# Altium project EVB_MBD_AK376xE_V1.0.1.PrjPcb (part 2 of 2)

## Sheet JTAG_I2S_KEY.SchDoc: EVB_MBD_AK376xE_V1.0.1
size A3; Revision: V1.0.1; SheetNumber: 8; SheetTotal: 8
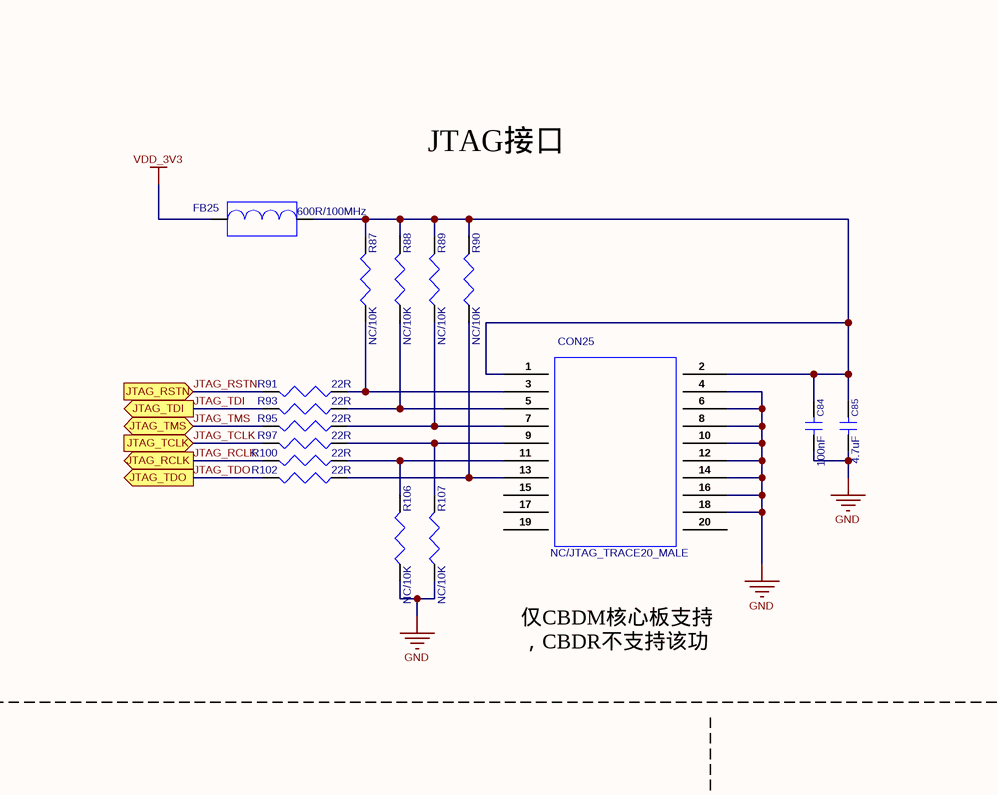
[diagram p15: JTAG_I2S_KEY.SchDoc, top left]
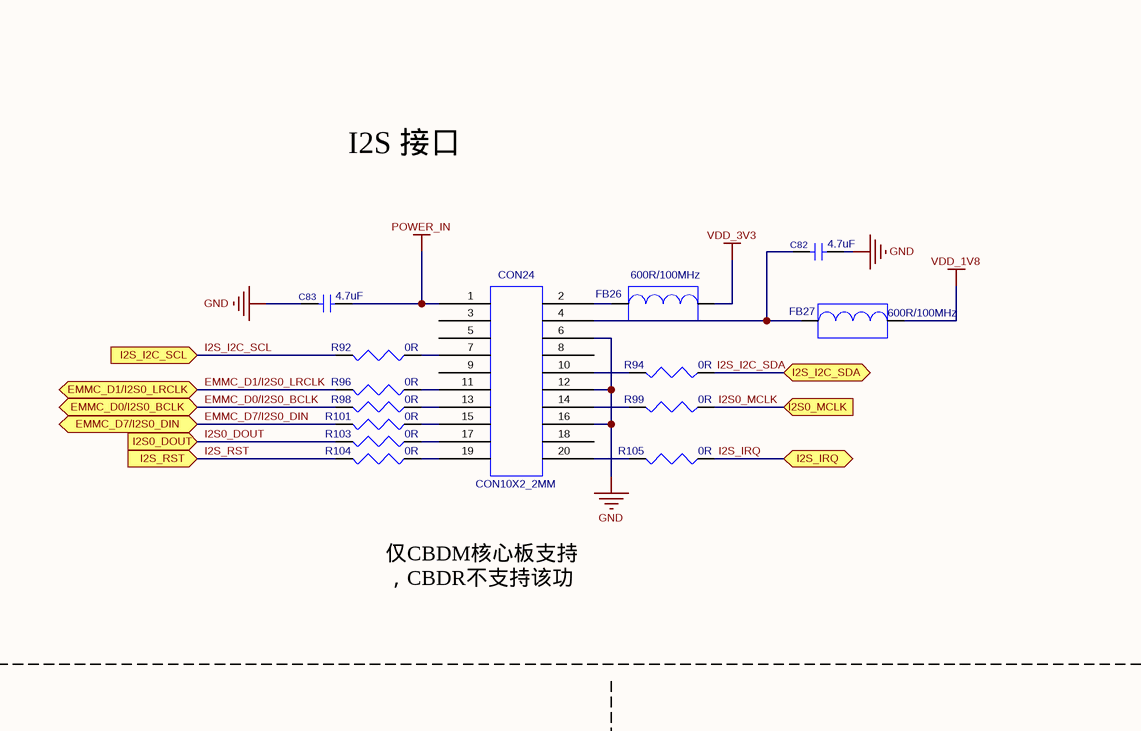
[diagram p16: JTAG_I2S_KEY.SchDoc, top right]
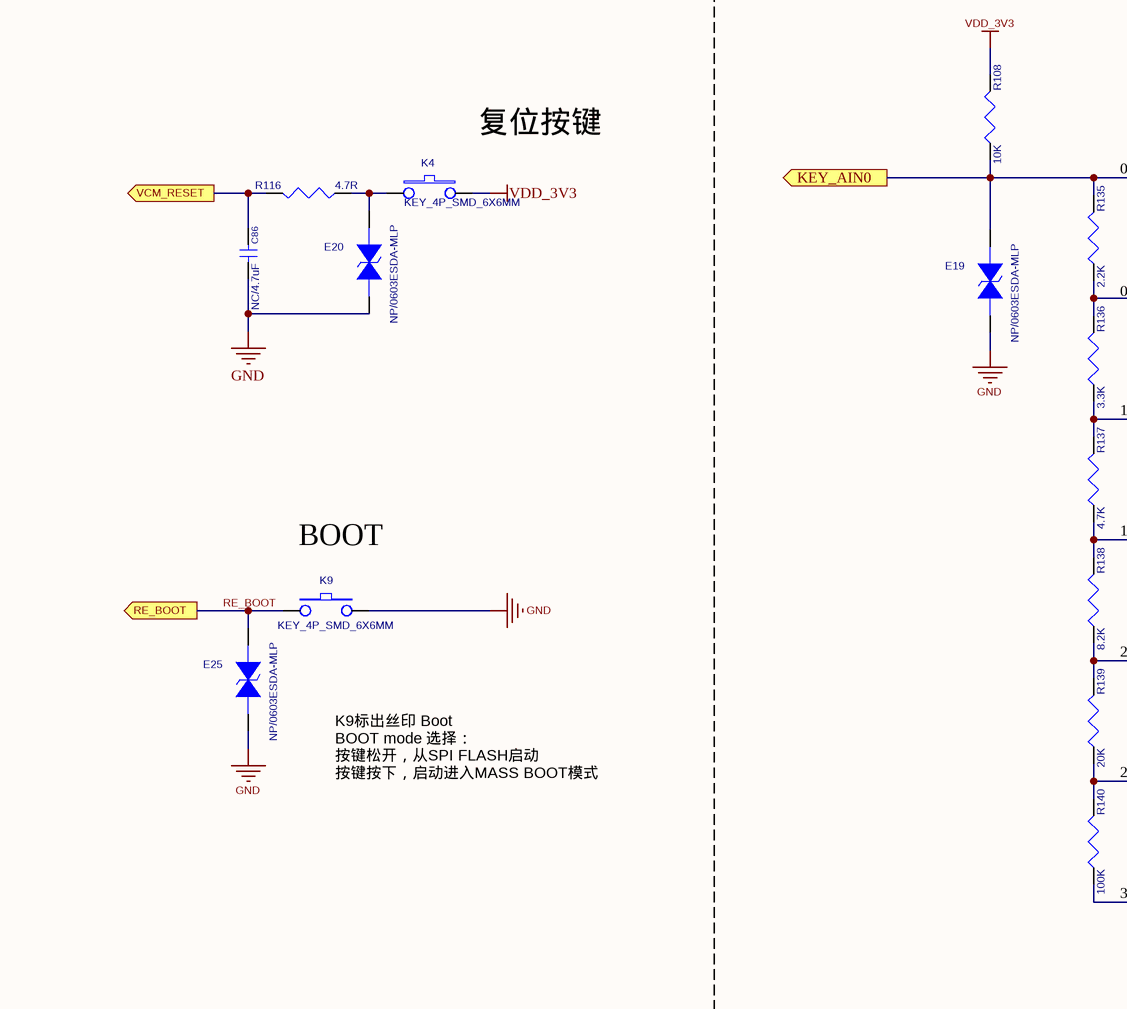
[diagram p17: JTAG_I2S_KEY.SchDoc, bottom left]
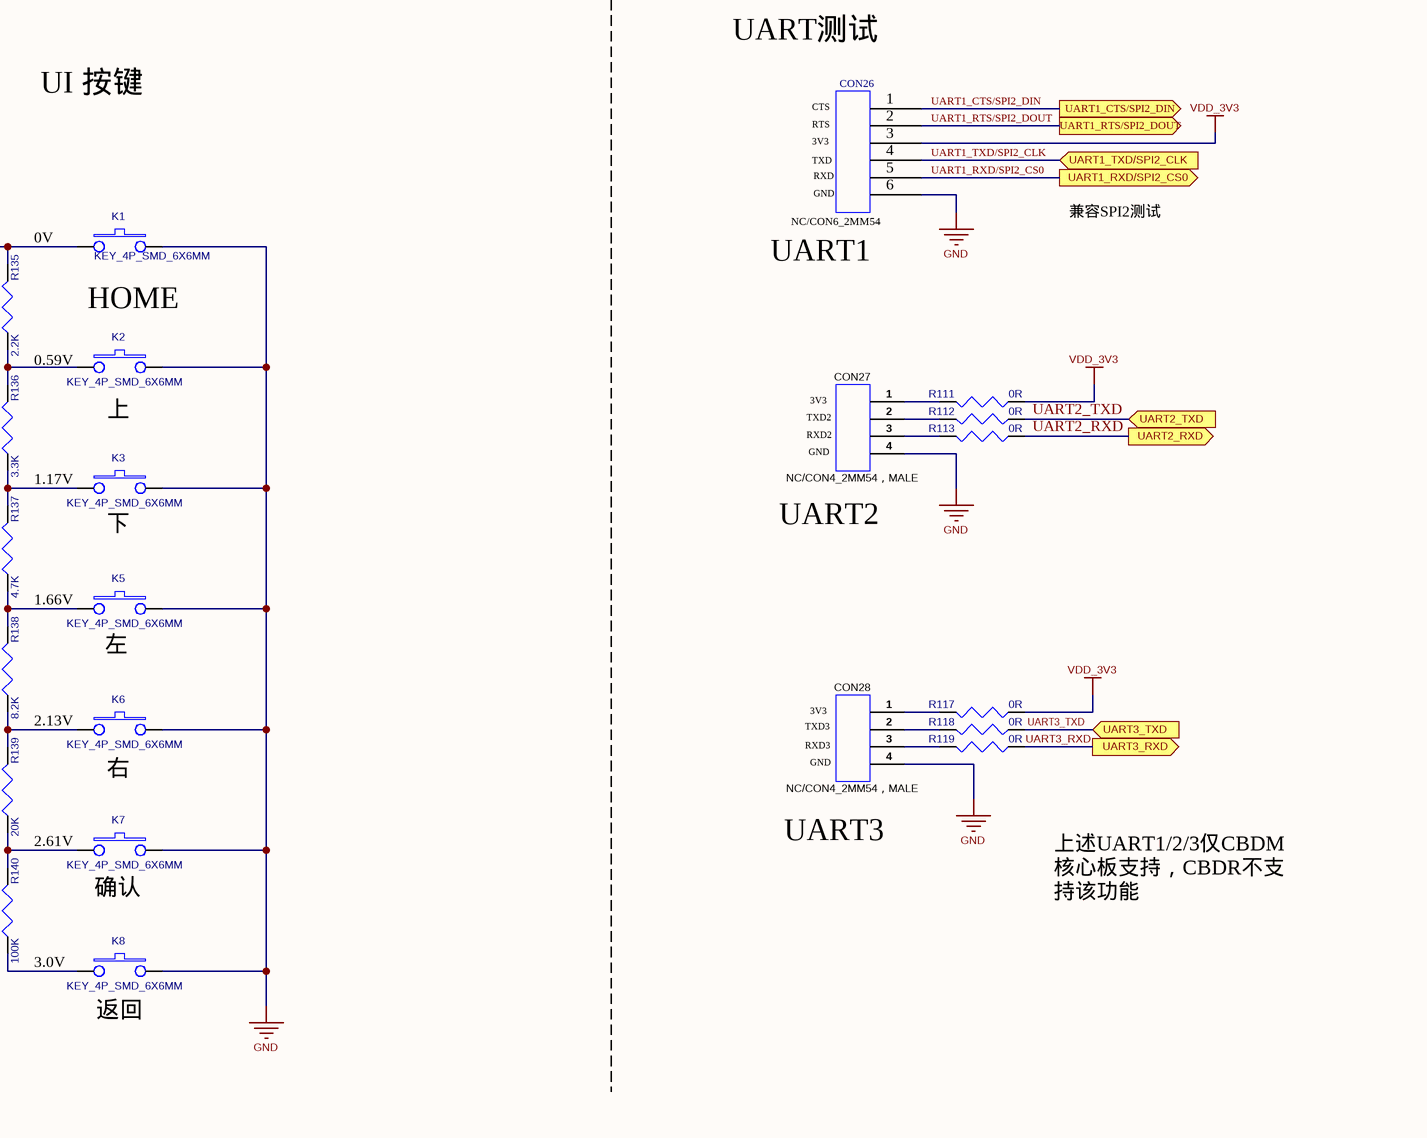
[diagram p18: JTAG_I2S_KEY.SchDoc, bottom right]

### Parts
C82  4.7uF  [C0603]
C83  4.7uF  [C0603]
C84  100nF  [C0603]
C85  4.7uF  [C0603]
C86  NC/4.7uF  [C0603]
CON24  value CON10X2_2MM  [CON10X2_2MM0]  (hidden comment: CON10X2_2MM0)
CON25  NC/JTAG_TRACE20_MALE  [JTAG_TRACE20_MALE]
CON26  NC/CON6_2MM54  [CON6_2MM54]
CON27  NC/CON4_2MM54，MALE  [CON4_2MM54]
CON28  NC/CON4_2MM54，MALE  [CON4_2MM54]
E19  value NP/0603ESDA-MLP  [ESD0603]  (hidden comment: ESD0603)
E20  value NP/0603ESDA-MLP  [ESD0603]  (hidden comment: ESD0603)
E25  value NP/0603ESDA-MLP  [ESD0603]  (hidden comment: ESD0603)
FB25  600R/100MHz  [FB0603]
FB26  600R/100MHz  [FB0603]
FB27  600R/100MHz  [FB0603]
K1  KEY_4P_SMD_6X6MM  [KEY_4P_SMD_6X6MM]
K2  KEY_4P_SMD_6X6MM  [KEY_4P_SMD_6X6MM]
K3  KEY_4P_SMD_6X6MM  [KEY_4P_SMD_6X6MM]
K4  KEY_4P_SMD_6X6MM  [KEY_4P_SMD_6X6MM]
K5  KEY_4P_SMD_6X6MM  [KEY_4P_SMD_6X6MM]
K6  KEY_4P_SMD_6X6MM  [KEY_4P_SMD_6X6MM]
K7  KEY_4P_SMD_6X6MM  [KEY_4P_SMD_6X6MM]
K8  KEY_4P_SMD_6X6MM  [KEY_4P_SMD_6X6MM]
K9  KEY_4P_SMD_6X6MM  [KEY_4P_SMD_6X6MM]
R87  NC/10K  [R0603]
R88  NC/10K  [R0603]
R89  NC/10K  [R0603]
R90  NC/10K  [R0603]
R91  22R  [R0603]
R92  0R  [R0603]
R93  22R  [R0603]
R94  0R  [R0603]
R95  22R  [R0603]
R96  0R  [R0603]
R97  22R  [R0603]
R98  0R  [R0603]
R99  0R  [R0603]
R100  22R  [R0603]
R101  0R  [R0603]
R102  22R  [R0603]
R103  0R  [R0603]
R104  0R  [R0603]
R105  0R  [R0603]
R106  NC/10K  [R0603]
R107  NC/10K  [R0603]
R108  10K  [R0603]
R111  0R  [R0603]
R112  0R  [R0603]
R113  0R  [R0603]
R116  4.7R  [R0603]
R117  0R  [R0603]
R118  0R  [R0603]
R119  0R  [R0603]
R135  2.2K  [R0603]
R136  3.3K  [R0603]
R137  4.7K  [R0603]
R138  8.2K  [R0603]
R139  20K  [R0603]
R140  100K  [R0603]

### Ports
EMMC_D0/I2S0_BCLK (bidir), EMMC_D1/I2S0_LRCLK (bidir), EMMC_D7/I2S0_DIN (bidir), I2S0_DOUT (in), I2S0_MCLK (in), I2S_I2C_SCL (in), I2S_I2C_SDA (bidir), I2S_IRQ (bidir), I2S_RST (in), JTAG_RCLK (out), JTAG_RSTN (in), JTAG_TCLK (in), JTAG_TDI (out), JTAG_TDO (out), JTAG_TMS (bidir), KEY_AIN0 (out), RE_BOOT (out), UART1_CTS/SPI2_DIN (out), UART1_RTS/SPI2_DOUT (out), UART1_RXD/SPI2_CS0 (out), UART1_TXD/SPI2_CLK (in), UART2_RXD (out), UART2_TXD (in), UART3_RXD (out), UART3_TXD (in), VCM_RESET (out)

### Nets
GND: C82.2 C83.1 C84.2 C85.2 C86.2 CON24.6 CON24.12 CON24.16 CON25.4 CON25.6 CON25.8 CON25.10 CON25.12 CON25.14 CON25.16 CON25.18 CON26.6 CON27.4 CON28.4 E19.2 E20.2 E25.2 K1.2 K2.2 K3.2 K5.2 K6.2 K7.2 K8.2 K9.1 R106.1 R107.1
POWER_IN: C83.2 CON24.1
VDD_1V8: FB27.2
VDD_3V3: CON26.3 FB25.1 FB26.2 K4.2 R108.2 R111.1 R117.1
EMMC_D0/I2S0_BCLK: R98.2 ; port EMMC_D0/I2S0_BCLK
EMMC_D1/I2S0_LRCLK: R96.2 ; port EMMC_D1/I2S0_LRCLK
EMMC_D7/I2S0_DIN: R101.2 ; port EMMC_D7/I2S0_DIN
I2S0_DOUT: R103.2 ; port I2S0_DOUT
I2S0_MCLK: R99.1 ; port I2S0_MCLK
I2S_I2C_SCL: R92.2 ; port I2S_I2C_SCL
I2S_I2C_SDA: R94.1 ; port I2S_I2C_SDA
I2S_IRQ: R105.1 ; port I2S_IRQ
I2S_RST: R104.2 ; port I2S_RST
JTAG_RCLK: R100.2 ; port JTAG_RCLK
JTAG_RSTN: R91.2 ; port JTAG_RSTN
JTAG_TCLK: R97.2 ; port JTAG_TCLK
JTAG_TDI: R93.2 ; port JTAG_TDI
JTAG_TDO: R102.2 ; port JTAG_TDO
JTAG_TMS: R95.2 ; port JTAG_TMS
RE_BOOT: E25.1 K9.2 ; port RE_BOOT
UART1_CTS/SPI2_DIN: CON26.1 ; port UART1_CTS/SPI2_DIN
UART1_RTS/SPI2_DOUT: CON26.2 ; port UART1_RTS/SPI2_DOUT
UART1_RXD/SPI2_CS0: CON26.5 ; port UART1_RXD/SPI2_CS0
UART1_TXD/SPI2_CLK: CON26.4 ; port UART1_TXD/SPI2_CLK
UART2_RXD: R113.1 ; port UART2_RXD
UART2_TXD: R112.1 ; port UART2_TXD
UART3_RXD: R119.1 ; port UART3_RXD
UART3_TXD: R118.1 ; port UART3_TXD
NetC82_1: C82.1 CON24.4 FB27.1
NetC84_1: C84.1 C85.1 CON25.1 CON25.2 FB25.2 R87.2 R88.2 R89.2 R90.2
NetC86_1: C86.1 R116.2 ; port VCM_RESET
NetCON1_1: E19.1 K1.1 R108.1 R135.2 ; port KEY_AIN0
NetCON24_2: CON24.2 FB26.1
NetCON24_7: CON24.7 R92.1
NetCON24_10: CON24.10 R94.2
NetCON24_11: CON24.11 R96.1
NetCON24_13: CON24.13 R98.1
NetCON24_14: CON24.14 R99.2
NetCON24_15: CON24.15 R101.1
NetCON24_17: CON24.17 R103.1
NetCON24_19: CON24.19 R104.1
NetCON24_20: CON24.20 R105.2
NetCON25_3: CON25.3 R87.1 R91.1
NetCON25_5: CON25.5 R88.1 R93.1
NetCON25_7: CON25.7 R89.1 R95.1
NetCON25_9: CON25.9 R97.1 R107.2
NetCON25_11: CON25.11 R100.1 R106.2
NetCON25_13: CON25.13 R90.1 R102.1
NetCON27_1: CON27.1 R111.2
NetCON27_2: CON27.2 R112.2
NetCON27_3: CON27.3 R113.2
NetCON28_1: CON28.1 R117.2
NetCON28_2: CON28.2 R118.2
NetCON28_3: CON28.3 R119.2
NetE20_1: E20.1 K4.1 R116.1
NetK2_1: K2.1 R135.1 R136.2
NetK3_1: K3.1 R136.1 R137.2
NetK5_1: K5.1 R137.1 R138.2
NetK6_1: K6.1 R138.1 R139.2
NetK7_1: K7.1 R139.1 R140.2
NetK8_1: K8.1 R140.1

Not connected (* = marked no-connect by the designer): CON24 3 5 8 9 18; CON25 15 17 19 20

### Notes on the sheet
- JTAG接口
- I2S 接口
- 仅CBDM核心板支持，CBDR不支持该功能
- UART测试
- UI 按键
- (near CON26) 3V3
- (near CON26) RTS
- (near CON26) CTS
- (near K4) 复位按键
- (near CON26) TXD
- (near CON26) RXD
- (near CON26) GND
- 兼容SPI2测试
- 0V
- HOME
- (near CON26) UART1
- 0.59V
- (near CON27) 3V3
- 1.17V
- (near K2) 上
- (near CON27) TXD2
- (near CON27) RXD2
- (near CON27) GND
- (near K3) 下
- (near CON27) UART2
- (near K9) BOOT
- (near K5) 1.66V
- (near K5) 左
- 2.13V
- (near CON28) TXD3
- (near CON28) RXD3
- (near CON28) 3V3
- K9标出丝印 Boot
- BOOT mode 选择：
- 按键松开，从SPI FLASH启动
- (near K6) 右
- (near CON28) GND
- 按键按下，启动进入MASS BOOT模式
- 2.61V
- (near K7) 确认
- (near CON28) UART3
- 上述UART1/2/3仅CBDM核心板支持，CBDR不支持该功能
- 3.0V
- (near K8) 返回

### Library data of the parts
C82 C83 C85 = CC0304750XX: C/C,4.7uF,25V,+/-5%,0603; Catalog: 陶瓷电容
C84 = CC0301040XX: C/C,100nF,25V,+/-5%,0603; Catalog: 陶瓷电容
C86 = CC0304750XX: C/C,4.7uF,25V,+/-5%,0603; Remark: NC; Catalog: 陶瓷电容
CON24 = CNHEF2001XX: Header,Female,CON10X2,2.0mm,20pin,排母; SOURCE_PATH: E:\工作目录\ORCAD原理图库\ORCAD元件库\CONNECTOR.OLB; Catalog: Connector
CON25 = CNHEM2000XX: Header,2X10pin,2.54mm,Male,排针; SOURCE_PATH: E:\工作目录\ORCAD原理图库\ORCAD元件库\CONNECTOR.OLB; PCB DECAL: JTAG_TRACE20_2MM54_MALE; Remark: NC; Catalog: Connector
CON26 = CNHEM0600XX: Header,Male,CON1X6,2.54mm,6pin，排针; Remark: NC; Catalog: Connector
CON27 CON28 = CNHEM0400XX: Header,1X4pin,2.54mm,Male，排针; Remark: NC; Catalog: Connector
E19 E20 E25 = ED0314000XX: PESD1608H140CR15GPT,0603; ROOM: power; Source_Path: F:\PROJECTFILES\CADENCE\AK9802PLATFORM\AK98XX_MB_V0-0715.DSN; Remark: NC; Catalog: ESD Protectors
FB25-FB27 = BE0306011XX: BLM18BD601SN1, 600R@100MHz; SOURCE_PATH: D:\PROGRAM FILES\ORCAD\ORCAD_10.5\TOOLS\CAPTURE\LIBRARY\DISCRETE.OLB; Catalog: 贴片磁珠
K1-K9 = SWKS04001XX: Catalog: 开关
R87-R90 R106 R107 = CR0310020XX: Res,10K,1/10W,+/-1%,0603; Remark: NC; Catalog: 贴片电阻
R91 R93 R95 R97 R100 R102 = CR0302200XX: Res,22R,1/10W,+/-5%,0603; Catalog: 贴片电阻
R92 R94 R96 R98 R99 R101 R103-R105 R111-R113 R117-R119 = CR0300000XX: Res,0R,1/10W,+/-5%,0603; Catalog: 贴片电阻
R108 = CR0310020XX: Res,10K,1/10W,+/-1%,0603; Catalog: 贴片电阻
R116 = CR0304R70XX: Res,4.7R,1/10W,+/-5%,0603; Catalog: 贴片电阻
R135 = CR0302221XX: Res,2.2K,1/10W,+/-1%,0603; Catalog: 贴片电阻
R136 = CR0333010XX: Res,3.3K,1/10W,+/-1%,0603; Catalog: 贴片电阻
R137 = CR0347010XX: Res,4.7K,1/10W,+/-1%,0603; Catalog: 贴片电阻
R138 = CR0308221XX: Res,8.2K,1/10W,+/-1%,0603; Catalog: 贴片电阻
R139 = CR0320020XX: Res,20K,1/10W,+/-1%,0603; Catalog: 贴片电阻
R140 = CR0310030XX: Res,100K,1/10W,+/-1%,0603; Catalog: 贴片电阻

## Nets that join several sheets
GND: INTERFACE_CORE (33 pins), POWER (52 pins), TF_PA_UART (64 pins), MAC_EMMC_USBWIFI (103 pins), LCD (44 pins), JTAG_I2S_KEY (32 pins)
POWER_IN: POWER (14 pins), TF_PA_UART (C55.1 FB14.1), LCD (FB28.1 Q5.D R122.1), JTAG_I2S_KEY (C83.2 CON24.1)
VCC_3V6: INTERFACE_CORE (CON2.2 CON2.4), POWER (9 pins)
VCC_RTC: INTERFACE_CORE (CON2.3 CON2.5), POWER (BT1.1)
VDD_1V8: POWER (C23.2 C24.1 U4.5), JTAG_I2S_KEY (FB27.2)
VDD_3V3: INTERFACE_CORE (CON2.8 CON2.10), POWER (8 pins), TF_PA_UART (5 pins), MAC_EMMC_USBWIFI (5 pins), LCD (R85.2 R123.1), JTAG_I2S_KEY (7 pins)
VDDIO_CSI: POWER (JP5.3), LCD (C89.1 CON29.2)
VDDIO_CSI0: INTERFACE_CORE (CON2.6), POWER (JP5.2)
WIFI_3V3: POWER (7 pins), MAC_EMMC_USBWIFI (FB18.1 FB19.1 FB22.1 FB23.1)
AK_DM: INTERFACE_CORE (CON1.40), POWER (CON7.2 JP1.2)
AK_DP: INTERFACE_CORE (CON1.38), POWER (CON7.3 JP2.2)
CSI0_I2C_SCL: INTERFACE_CORE (CON2.36), LCD (CON29.8)
CSI0_I2C_SDA: INTERFACE_CORE (CON2.35), LCD (CON29.7)
CSI0_PCLK: INTERFACE_CORE (CON2.38), LCD (CON29.11)
CSI0_PDWN: INTERFACE_CORE (CON2.33), LCD (CON29.6)
CSI0_REST: INTERFACE_CORE (CON2.34), LCD (CON29.5)
CSI0_SCLK: INTERFACE_CORE (CON2.37), LCD (CON29.12)
EMMC_CLK: INTERFACE_CORE (CON2.21), MAC_EMMC_USBWIFI (R63.2)
EMMC_CMD: INTERFACE_CORE (CON2.18), MAC_EMMC_USBWIFI (R64.1)
EMMC_D0/I2S0_BCLK: INTERFACE_CORE (CON2.24), MAC_EMMC_USBWIFI (R47.1), JTAG_I2S_KEY (R98.2)
EMMC_D1/I2S0_LRCLK: INTERFACE_CORE (CON2.22), MAC_EMMC_USBWIFI (R46.2), JTAG_I2S_KEY (R96.2)
EMMC_D2: INTERFACE_CORE (CON2.15), MAC_EMMC_USBWIFI (R61.2)
EMMC_D3: INTERFACE_CORE (CON2.16), MAC_EMMC_USBWIFI (R62.1)
EMMC_D4: INTERFACE_CORE (CON2.17), MAC_EMMC_USBWIFI (R51.2)
EMMC_D5: INTERFACE_CORE (CON2.19), MAC_EMMC_USBWIFI (R52.1)
EMMC_D6: INTERFACE_CORE (CON2.20), MAC_EMMC_USBWIFI (R59.2)
EMMC_D7/I2S0_DIN: INTERFACE_CORE (CON2.23), MAC_EMMC_USBWIFI (R60.1), JTAG_I2S_KEY (R101.2)
EMMC_RST: INTERFACE_CORE (CON3.35), MAC_EMMC_USBWIFI (R65.2)
HPOUT: INTERFACE_CORE (CON1.4), TF_PA_UART (C53.1)
I2S0_DOUT: INTERFACE_CORE (CON2.26), JTAG_I2S_KEY (R103.2)
I2S0_MCLK: INTERFACE_CORE (CON2.25), JTAG_I2S_KEY (R99.1)
I2S_I2C_SCL: INTERFACE_CORE (CON3.50), JTAG_I2S_KEY (R92.2)
I2S_I2C_SDA: INTERFACE_CORE (CON3.49), JTAG_I2S_KEY (R94.1)
I2S_IRQ: INTERFACE_CORE (CON3.48), JTAG_I2S_KEY (R105.1)
I2S_RST: INTERFACE_CORE (CON3.47), JTAG_I2S_KEY (R104.2)
JTAG_RCLK: INTERFACE_CORE (CON4.4), JTAG_I2S_KEY (R100.2)
JTAG_RSTN: INTERFACE_CORE (CON4.2), JTAG_I2S_KEY (R91.2)
JTAG_TCLK: INTERFACE_CORE (CON4.3), JTAG_I2S_KEY (R97.2)
JTAG_TDI: INTERFACE_CORE (CON4.1), JTAG_I2S_KEY (R93.2)
JTAG_TDO: INTERFACE_CORE (CON4.5), JTAG_I2S_KEY (R102.2)
JTAG_TMS: INTERFACE_CORE (CON4.6), JTAG_I2S_KEY (R95.2)
LCD_BL: INTERFACE_CORE (CON3.34), LCD (CON22.20 CON23.8)
LCD_D0: INTERFACE_CORE (CON3.8), LCD (CON23.16)
LCD_D1: INTERFACE_CORE (CON3.7), LCD (CON23.17)
LCD_D2: INTERFACE_CORE (CON3.10), LCD (CON23.18)
LCD_D3: INTERFACE_CORE (CON3.9), LCD (CON23.19)
LCD_D4: INTERFACE_CORE (CON3.12), LCD (CON23.20)
LCD_D5: INTERFACE_CORE (CON3.11), LCD (CON23.21)
LCD_D6: INTERFACE_CORE (CON3.14), LCD (CON23.22)
LCD_D7: INTERFACE_CORE (CON3.13), LCD (CON23.23)
LCD_D8: INTERFACE_CORE (CON3.16), LCD (CON23.25)
LCD_D9: INTERFACE_CORE (CON3.15), LCD (CON23.26)
LCD_D10: INTERFACE_CORE (CON3.18), LCD (CON23.27)
LCD_D11: INTERFACE_CORE (CON3.17), LCD (CON23.28)
LCD_D12: INTERFACE_CORE (CON3.20), LCD (CON23.29)
LCD_D13: INTERFACE_CORE (CON3.19), LCD (CON23.30)
LCD_D14: INTERFACE_CORE (CON3.22), LCD (CON23.31)
LCD_D15: INTERFACE_CORE (CON3.21), LCD (CON23.32)
LCD_D16: INTERFACE_CORE (CON3.24), LCD (CON23.34)
LCD_D17: INTERFACE_CORE (CON3.23), LCD (CON23.35)
LCD_D18: INTERFACE_CORE (CON3.26), LCD (CON23.36)
LCD_D19: INTERFACE_CORE (CON3.25), LCD (CON23.37)
LCD_D20: INTERFACE_CORE (CON3.28), LCD (CON23.38)
LCD_D21: INTERFACE_CORE (CON3.27), LCD (CON23.39)
LCD_D22: INTERFACE_CORE (CON3.30), LCD (CON23.40)
LCD_D23: INTERFACE_CORE (CON3.29), LCD (CON23.41)
LCD_PWR: INTERFACE_CORE (CON3.40), LCD (R124.1)
LCD_RST: INTERFACE_CORE (CON3.33), LCD (CON22.1 CON23.10)
LED_CON: INTERFACE_CORE (CON3.36), LCD (CON29.3)
LED_STATE: INTERFACE_CORE (CON3.46), LCD (R86.2)
MIPI_DSI_TXDN0: INTERFACE_CORE (CON1.8), LCD (CON22.3)
MIPI_DSI_TXDN1: INTERFACE_CORE (CON1.14), LCD (CON22.6)
MIPI_DSI_TXDN2: INTERFACE_CORE (CON1.20), LCD (CON22.9)
MIPI_DSI_TXDN3: INTERFACE_CORE (CON1.26), LCD (CON22.12)
MIPI_DSI_TXDN4: INTERFACE_CORE (CON1.32), LCD (CON22.15)
MIPI_DSI_TXDP0: INTERFACE_CORE (CON1.10), LCD (CON22.4)
MIPI_DSI_TXDP1: INTERFACE_CORE (CON1.16), LCD (CON22.7)
MIPI_DSI_TXDP2: INTERFACE_CORE (CON1.22), LCD (CON22.10)
MIPI_DSI_TXDP3: INTERFACE_CORE (CON1.28), LCD (CON22.13)
MIPI_DSI_TXDP4: INTERFACE_CORE (CON1.34), LCD (CON22.16)
NetC86_1: INTERFACE_CORE (CON1.2), JTAG_I2S_KEY (C86.1 R116.2)
NetCON1_1: INTERFACE_CORE (CON1.1), JTAG_I2S_KEY (E19.1 K1.1 R108.1 R135.2)
NetCON2_39: INTERFACE_CORE (CON2.39), LCD (R69.2 R134.2)
NetCON2_40: INTERFACE_CORE (CON2.40), LCD (R70.2 R133.2)
NetCON2_41: INTERFACE_CORE (CON2.41), LCD (R79.2 R132.2)
NetCON2_43: INTERFACE_CORE (CON2.43), LCD (R80.2 R131.2)
NetCON2_44: INTERFACE_CORE (CON2.44), LCD (R78.2 R130.2)
NetCON2_46: INTERFACE_CORE (CON2.46), LCD (R77.2 R129.2)
NetCON2_47: INTERFACE_CORE (CON2.47), LCD (R68.2 R128.2)
NetCON2_48: INTERFACE_CORE (CON2.48), LCD (R75.2 R127.2)
NetCON2_49: INTERFACE_CORE (CON2.49), LCD (R74.2 R126.2)
NetCON2_50: INTERFACE_CORE (CON2.50), LCD (R71.2 R125.2)
RE_BOOT: INTERFACE_CORE (CON1.39), JTAG_I2S_KEY (E25.1 K9.2)
RGB_PCLK/MPU_WR: INTERFACE_CORE (CON3.3), LCD (CON23.11)
RGB_VOGATE/MPU_RD: INTERFACE_CORE (CON3.2), LCD (CON23.14)
RGB_VOHSYNC/MPU_CS: INTERFACE_CORE (CON3.4), LCD (CON23.12)
RGB_VOVSYNC/MPU_A0: INTERFACE_CORE (CON3.1), LCD (CON23.13)
RMII0_50MCLK: INTERFACE_CORE (CON4.22), MAC_EMMC_USBWIFI (CON12.8)
RMII0_MDC: INTERFACE_CORE (CON4.15), MAC_EMMC_USBWIFI (CON12.9)
RMII0_MDIO: INTERFACE_CORE (CON4.14), MAC_EMMC_USBWIFI (CON12.10)
RMII0_RST: INTERFACE_CORE (CON2.11), MAC_EMMC_USBWIFI (CON12.30)
RMII0_RXD0: INTERFACE_CORE (CON4.18), MAC_EMMC_USBWIFI (CON12.25)
RMII0_RXD1: INTERFACE_CORE (CON4.19), MAC_EMMC_USBWIFI (CON12.26)
RMII0_RXDV: INTERFACE_CORE (CON4.17), MAC_EMMC_USBWIFI (CON12.27)
RMII0_RXER: INTERFACE_CORE (CON4.16), MAC_EMMC_USBWIFI (CON12.28)
RMII0_TXD0: INTERFACE_CORE (CON4.23), MAC_EMMC_USBWIFI (CON12.15)
RMII0_TXD1: INTERFACE_CORE (CON4.26), MAC_EMMC_USBWIFI (CON12.16)
RMII0_TXEN: INTERFACE_CORE (CON4.25), MAC_EMMC_USBWIFI (CON12.11)
RMII1_50MCLK: MAC_EMMC_USBWIFI (CON17.8), LCD (R68.1)
RMII1_MDC/SD2_D0: MAC_EMMC_USBWIFI (CON17.9), LCD (R70.1)
RMII1_MDIO/SD2_D1: MAC_EMMC_USBWIFI (CON17.10), LCD (R69.1)
RMII1_RST: INTERFACE_CORE (CON2.12), MAC_EMMC_USBWIFI (CON17.30)
RMII1_RXD0/SD2_D3: MAC_EMMC_USBWIFI (CON17.25), LCD (R78.1)
RMII1_RXD1/SD2_D2: MAC_EMMC_USBWIFI (CON17.26), LCD (R77.1)
RMII1_RXDV/SD2_CMD: MAC_EMMC_USBWIFI (CON17.27), LCD (R80.1)
RMII1_RXER/SD2_CLK: MAC_EMMC_USBWIFI (CON17.28), LCD (R79.1)
RMII1_TXD0: MAC_EMMC_USBWIFI (CON17.15), LCD (R75.1)
RMII1_TXD1: MAC_EMMC_USBWIFI (CON17.16), LCD (R74.1)
RMII1_TXEN: MAC_EMMC_USBWIFI (CON17.11), LCD (R71.1)
SPK_EN: INTERFACE_CORE (CON3.45), TF_PA_UART (R30.2)
TF_CMD: INTERFACE_CORE (CON4.33), TF_PA_UART (R22.1)
TF_D0: INTERFACE_CORE (CON4.29), TF_PA_UART (R25.1)
TF_D1: INTERFACE_CORE (CON4.30), TF_PA_UART (R26.1)
TF_D2: INTERFACE_CORE (CON4.35), TF_PA_UART (R20.1)
TF_D3: INTERFACE_CORE (CON4.36), TF_PA_UART (R21.1)
TF_DET: INTERFACE_CORE (CON3.37), TF_PA_UART (R28.1)
TF_EN: INTERFACE_CORE (CON3.39), TF_PA_UART (R27.2)
TF_MCK: INTERFACE_CORE (CON4.34), TF_PA_UART (R24.1)
TS_INT: INTERFACE_CORE (CON2.32), LCD (CON22.24 CON23.50)
TS_RST: INTERFACE_CORE (CON2.31), LCD (CON22.25 CON23.47)
TS_SCL: INTERFACE_CORE (CON2.30), LCD (CON22.22 CON23.48)
TS_SDA: INTERFACE_CORE (CON2.29), LCD (CON22.23 CON23.49)
UART0_RXD: INTERFACE_CORE (CON4.27), TF_PA_UART (CON32.3 CON33.3)
UART0_TXD: INTERFACE_CORE (CON4.28), TF_PA_UART (CON32.2 CON33.2)
UART1_CTS/SPI2_DIN: INTERFACE_CORE (CON4.10), JTAG_I2S_KEY (CON26.1)
UART1_RTS/SPI2_DOUT: INTERFACE_CORE (CON4.9), JTAG_I2S_KEY (CON26.2)
UART1_RXD/SPI2_CS0: INTERFACE_CORE (CON4.8), JTAG_I2S_KEY (CON26.5)
UART1_TXD/SPI2_CLK: INTERFACE_CORE (CON4.7), JTAG_I2S_KEY (CON26.4)
UART2_RXD: INTERFACE_CORE (CON4.38), JTAG_I2S_KEY (R113.1)
UART2_TXD: INTERFACE_CORE (CON4.40), JTAG_I2S_KEY (R112.1)
UART3_RXD: INTERFACE_CORE (CON4.37), JTAG_I2S_KEY (R119.1)
UART3_TXD: INTERFACE_CORE (CON4.39), JTAG_I2S_KEY (R118.1)
WIFI_DM: POWER (JP1.3), MAC_EMMC_USBWIFI (CON20.12)
WIFI_DP: POWER (JP2.3), MAC_EMMC_USBWIFI (CON20.14)
WIFI_EN: INTERFACE_CORE (CON3.42), POWER (R10.2)
WIFI_INT: INTERFACE_CORE (CON3.41), MAC_EMMC_USBWIFI (CON12.14 CON17.14 R48.2)
WIFI_RST: INTERFACE_CORE (CON3.38), MAC_EMMC_USBWIFI (CON12.13 CON17.13 R49.1)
